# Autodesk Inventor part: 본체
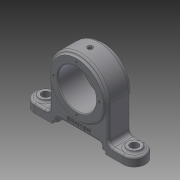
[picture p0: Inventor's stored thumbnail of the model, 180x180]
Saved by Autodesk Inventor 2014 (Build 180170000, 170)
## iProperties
Created: 2019-05
Part Number: 본체
Material: Generic
Document SubType Name: Modeling
Designer: kh
Density: 1 g/cm^3
Appearance: Default
Author: kh
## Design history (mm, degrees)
sketch "Sketch1"
  geometry: L1 (-60, 0)-(60, 0); L2 (-60, 15)-(60, 15); L3 (60, -15)-(-60, -15); A1 r 15 centre (-60, 0) between (-60, 15) and (-60, -15); A2 r 15 centre (60, 0) between (60, -15) and (60, 15); 2 further points
  constraints: 8 end point, 4 point on circle, 4 tangent, 2 centre point, 1 coincident, 1 horizontal, 1 midpoint, 1 parallel
  dimensions: "d0" = 120 distance of L1.start L1.end; "d1" = 15 radius of A2
extrude "Extrusion1" new body sketch "Sketch1" distance "d2" = 12; taper "d3" = 0 deg
sketch "Sketch2"
  geometry: L1 (120, 0)-(0, 0) reference; L2 (120, 0)-(120, 12) reference; L3 (0, 12)-(120, 12) reference; L4 (0, 0)-(0, 12) reference; L5 (0, 0)-(0, 0) reference; L6 (0, 0)-(0, 12) reference; L7 (0, 12)-(0, 12) reference; L8 (0, 0)-(0, 12) reference; L9 (120, 0)-(120, 0) reference; L10 (120, 0)-(120, 12) reference; L11 (120, 12)-(120, 12) reference; L12 (120, 0)-(120, 12) reference; L13 (-15, 0)-(-15, 12) reference; L14 (135, 0)-(135, 12) reference; L15 (24, 4)-(96, 4); L16 (96, 4)-(96, 0); L17 (96, 0)-(24, 0); L18 (24, 0)-(24, 4); 2 further points
  constraints: 8 end point, 2 midpoint, 2 parallel, 1 horizontal, 1 perpendicular
  dimensions: "d4" = 72 distance of L16.end L17.end; "d5" = 4 distance of L15.end L16.end
extrude "Extrusion2" cut sketch "Sketch2" stored distance "d6" = 12; taper "d7" = 0 deg
sketch "Sketch3"
  geometry: L1 (96, -8)-(96, -12) reference; L2 (120, -12)-(96, -12) reference; L3 (120, -12)-(120, 0) reference; L4 (0, 0)-(120, 0) reference; L5 (0, -12)-(0, 0) reference; L6 (24, -12)-(0, -12) reference; L7 (24, -12)-(24, -8) reference; L8 (24, -8)-(96, -8) reference; L9 (60, -12)-(60, -8); L10 (30, -2)-(90, -2); L11 (90, -2)-(90, -8); L12 (90, -8)-(30, -8); L13 (30, -8)-(30, -2); L14 (24, -8)-(96, -8) reference; 1 further point
  constraints: 10 end point, 3 midpoint, 2 parallel, 1 horizontal, 1 perpendicular
  dimensions: "d8" = 60 distance of L11.end L12.end; "d9" = 6 distance of L10.end L11.end
extrude "Extrusion3" cut sketch "Sketch3" stored distance "d10" = 12; taper "d11" = 0 deg
sketch "Sketch4"
  geometry: L1 (-15, 0)-(15, 0) reference; L2 (-15, 0)-(-15, 12) reference; L3 (15, 12)-(-15, 12) reference; L4 (15, 0)-(15, 12) reference; L5 (-18, 60)-(-18, 96); L6 (-18, 96)-(18, 96); L7 (18, 96)-(18, 60); L8 (18, 60)-(-18, 60); L9 (-18, 86)-(18, 86); 3 further points
  constraints: 10 end point, 3 parallel, 2 midpoint, 2 perpendicular, 2 point on line, 1 vertical alignment
  dimensions: "d12" = 72 diameter of L6 L8; "d13" = 60 vertical distance of L5.start L1.start; "d14" = 52 diameter of L9 L8; "d15" = 36 distance of L5.end L6.end
revolve "Revolution1" sketch "Sketch4" stored, may be unused: angle "d16" = 90 deg
sketch "Sketch5"
  geometry: L1 (-30, 4)-(-30, 10) reference; L2 (-30, 10)-(30, 10) reference; L3 (30, 10)-(30, 4) reference; L4 (30, 4)-(36, 4) reference; L5 (36, 4)-(36, 0) reference; L6 (60, 0)-(36, 0) reference; L7 (60, 0)-(60, 12) reference; L8 (-60, 12)-(60, 12) reference; L9 (-60, 0)-(-60, 12) reference; L10 (-36, 0)-(-60, 0) reference; L11 (-36, 0)-(-36, 4) reference; L12 (-36, 4)-(-30, 4) reference; L13 (60, 0)-(60, 0) reference; L14 (60, 0)-(60, 12) reference; L15 (60, 12)-(60, 12) reference; L16 (60, 0)-(60, 12) reference; L17 (-60, 0)-(-60, 0) reference; L18 (-60, 0)-(-60, 12) reference; L19 (-60, 12)-(-60, 12) reference; L20 (-60, 0)-(-60, 12) reference; L21 (75, 0)-(75, 12) reference; L22 (-75, 0)-(-75, 12) reference; L23 (40, 60)-(40, 12); L24 (-40, 60)-(-40, 12); L25 (40, 12)-(-40, 12); C1 r 36 at (0, 60) reference; C2 r 26 at (0, 60) reference; A1 r 40 centre (0, 60) between (40, 60) and (-40, 60); 1 further point
  constraints: 6 end point, 2 perpendicular, 2 point on circle, 2 point on line, 2 tangent, 1 centre point, 1 coincident, 1 parallel
  dimensions: "d17" = 80 diameter of A1
extrude "Extrusion4" join sketch "Sketch5" stored distance "d18" = 30; taper "d19" = 0 deg
sketch "Sketch6"
  geometry: L1 (-40, -15)-(-40, 15) reference; L2 (-40, 15)-(-60, 15) reference; L3 (-60, -15)-(-40, -15) reference; L4 (40, 15)-(40, -15) reference; L5 (40, -15)-(60, -15) reference; L6 (60, 15)-(40, 15) reference; C1 r 9 at (-60, 0); C2 r 9 at (60, 0); A1 r 15 centre (-60, 0) between (-60, 15) and (-60, -15) reference; A2 r 15 centre (60, 0) between (60, -15) and (60, 15) reference; 1 further point
  constraints: 2 centre point, 2 coincident
  dimensions: "d20" = 18 diameter of C1; "d21" = 18 diameter of C2
extrude "Extrusion5" join sketch "Sketch6" distance "d22" = 3; taper "d23" = 0 deg
hole "Hole1" diameter "d26" = 11; stored, may be unused: countersink angle "d30" = 90 deg, drill point angle "d32" = 118 deg; dims "d24" = 10, "d25" = 10, "d27" = 6, "d28" = 4, "d29" = 2, "d31" = 8
hole "Hole2" diameter "d35" = 11; stored, may be unused: countersink angle "d39" = 90 deg, drill point angle "d41" = 118 deg; dims "d33" = 10, "d34" = 10, "d36" = 6, "d37" = 4, "d38" = 2, "d40" = 8
workplane "Work Plane1"
sketch "Sketch7"
  geometry: 2 further points
  constraints: 1 coincident
hole "Hole3" sketch "Sketch7" at (0, 0) diameter "d42" = 4.917; stored, may be unused: countersink angle "d46" = 90 deg, drill point angle "d48" = 118 deg; dims "d43" = 8, "d44" = 7, "d45" = 1, "d47" = 10
sketch "Sketch8"
  geometry: C1 r 26 at (0, 0) reference; 1 further point
extrude "Extrusion6" cut sketch "Sketch8" stored distance "d49" = 3; taper "d50" = 0 deg
sketch "Sketch9"
  geometry: C1 r 1 at (0, 0); 1 further point
  constraints: 1 centre point, 1 coincident
  dimensions: "d51" = 2 diameter of C1
extrude "Extrusion7" cut sketch "Sketch9" stored distance "d52" = 3; taper "d53" = 0 deg
sketch "Sketch10"
  geometry: L1 (0, 0)-(0, 31); C1 r 26 at (0, 0) reference; C2 r 36 at (0, 0) reference; 2 further points
  constraints: 2 end point, 1 coincident, 1 vertical
  dimensions: "d54" = 31 distance of L1.start L1.end
hole "Hole4" sketch "Sketch10" at (0, 31), (0, -60), (0, 0) diameter "d55" = 3.242; stored, may be unused: countersink angle "d59" = 90 deg, drill point angle "d61" = 118 deg; dims "d56" = 6, "d57" = 7, "d58" = 1, "d60" = 8
pattern_circular "Circular Pattern1" dims angle "d63" = 360 deg
mirror "Mirror1"
sketch "Sketch11"
  geometry: L1 (-76.592, 19.402)-(-43.408, 19.402); L2 (-43.408, 19.402)-(-43.408, 14.598); L3 (-43.408, 14.598)-(-76.592, 14.598); L4 (-76.592, 14.598)-(-76.592, 19.402); L5 (-76.592, 19.402)-(-43.408, 14.598); L6 (-90, 10)-(-30, 10) reference; 2 further points
  constraints: 2 end point, 1 midpoint, 1 vertical alignment, 2 other
  dimensions: "d65" = 7 distance from line of point (-60, 17) L6
emboss "Emboss1" sketch "Sketch11" dims "d66" = 0.5, "d67" = 0
chamfer "Chamfer1" distance "d68" = 1; stored, may be unused: second distance "d69" = 2, angle "d70" = 45 deg
fillet "Fillet1" dims "d71" = 3
fillet "Fillet3" dims "d73" = 3
workplane "Work Plane2"
sketch "Sketch12"
  geometry: C1 r 1.5 at (0, 86); 2 further points
  constraints: 2 vertical alignment, 1 centre point, 1 other
  dimensions: "d75" = 3 diameter of C1
extrude "Extrusion8" cut sketch "Sketch12" stored distance "d76" = 3; taper "d77" = 0 deg
fillet "Fillet4" dims "d78" = 3
fillet "Fillet5" dims "d79" = 6
fillet "Fillet6" dims "d80" = 3
fillet "Fillet7" dims "d81" = 6
fillet "Fillet8" dims "d82" = 3
fillet "Fillet9" dims "d83" = 3
body "Solid1"
node "Projected Loop1"
node "Projected Loop2"
node "Projected Loop3"
node "Projected Loop4"
node "Projected Loop5"
node "Projected Loop6"
node "Projected Loop7"
node "Projected Loop8"
node "Projected Loop9"
node "Projected Loop10"
node "Projected Loop11"
node "Projected Loop12"
node "Projected Loop13"
other parameters: "d74" = -28.25
